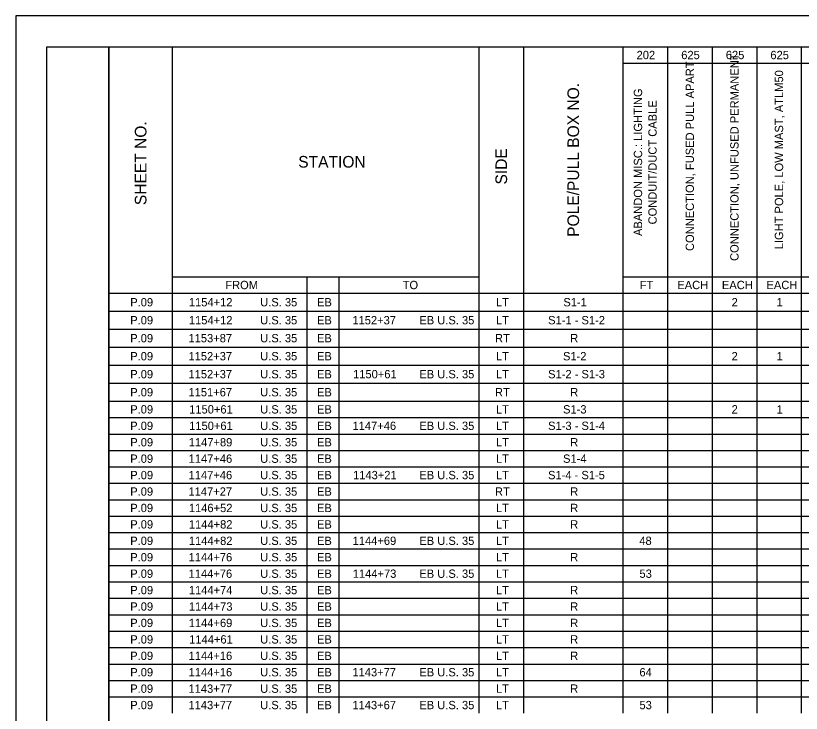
# Model space of a CAD drawing. Extents: x 0 to 34, y 0 to 22.
# Drawn here: x 0 to 12.63, y 10.78 to 22 of the extents above; entities that cross this region are included whole.
import ezdxf

# ---------------------------------------------------------------- set-up
doc = ezdxf.new("R2010")
doc.units = 0
for name, color, linetype in [('Default', 7, 'Continuous'), ('SH_Border', 7, 'Continuous'), ('SH_Cut_Line', 7, 'Continuous')]:
    doc.layers.add(name, color=color, linetype=linetype)

msp = doc.modelspace()

# ---------------------------------------------------------------- linework, layer by layer
at = {"layer": 'Default'}
for p, q in [((1.5, 21.5), (2.519, 21.5)), ((1.5, 21.5), (1.5, 21.236)), ((2.519, 21.5), (4.683, 21.5)), ((2.519, 21.5), (2.519, 21.236)), ((4.683, 21.5), (11.918, 21.5)), ((7.451, 21.5), (7.451, 21.236)), ((8.168, 21.5), (8.168, 21.236)), ((9.766, 21.5), (9.766, 21.236)), ((10.483, 21.5), (10.483, 21.236)), ((11.201, 21.5), (11.201, 21.236)), ((11.918, 21.5), (12.635, 21.5)), ((11.918, 21.5), (11.918, 21.236)), ((12.635, 21.5), (13.352, 21.5)), ((12.635, 21.5), (12.635, 21.236)), ((1.5, 21.236), (1.5, 20.972)), ((2.519, 21.236), (2.519, 20.972)), ((7.451, 21.236), (7.451, 20.972)), ((8.168, 21.236), (8.168, 20.972)), ((9.766, 21.236), (11.918, 21.236)), ((9.766, 21.236), (9.766, 20.972)), ((10.483, 21.236), (10.483, 20.972)), ((11.201, 21.236), (11.201, 20.972)), ((11.918, 21.236), (12.635, 21.236)), ((11.918, 21.236), (11.918, 20.972)), ((12.635, 21.236), (13.352, 21.236)), ((12.635, 21.236), (12.635, 20.972)), ((1.5, 20.972), (1.5, 20.707)), ((2.519, 20.972), (2.519, 20.707)), ((7.451, 20.972), (7.451, 20.707)), ((8.168, 20.972), (8.168, 20.707)), ((9.766, 20.972), (9.766, 20.707)), ((10.483, 20.972), (10.483, 20.707)), ((11.201, 20.972), (11.201, 20.707)), ((11.918, 20.972), (11.918, 20.707)), ((12.635, 20.972), (12.635, 20.707)), ((1.5, 20.707), (1.5, 20.443)), ((2.519, 20.707), (2.519, 20.443)), ((7.451, 20.707), (7.451, 20.443)), ((8.168, 20.707), (8.168, 20.443)), ((9.766, 20.707), (9.766, 20.443)), ((10.483, 20.707), (10.483, 20.443)), ((11.201, 20.707), (11.201, 20.443)), ((11.918, 20.707), (11.918, 20.443)), ((12.635, 20.707), (12.635, 20.443)), ((1.5, 20.443), (1.5, 20.179)), ((2.519, 20.443), (2.519, 20.179)), ((7.451, 20.443), (7.451, 20.179)), ((8.168, 20.443), (8.168, 20.179)), ((9.766, 20.443), (9.766, 20.179)), ((10.483, 20.443), (10.483, 20.179)), ((11.201, 20.443), (11.201, 20.179)), ((11.918, 20.443), (11.918, 20.179)), ((12.635, 20.443), (12.635, 20.179)), ((1.5, 20.179), (1.5, 19.915)), ((2.519, 20.179), (2.519, 19.915)), ((7.451, 20.179), (7.451, 19.915)), ((8.168, 20.179), (8.168, 19.915)), ((9.766, 20.179), (9.766, 19.915)), ((10.483, 20.179), (10.483, 19.915)), ((11.201, 20.179), (11.201, 19.915)), ((11.918, 20.179), (11.918, 19.915)), ((12.635, 20.179), (12.635, 19.915)), ((1.5, 19.915), (1.5, 19.651)), ((2.519, 19.915), (2.519, 19.651)), ((7.451, 19.915), (7.451, 19.651)), ((8.168, 19.915), (8.168, 19.651)), ((9.766, 19.915), (9.766, 19.651)), ((10.483, 19.915), (10.483, 19.651)), ((11.201, 19.915), (11.201, 19.651)), ((11.918, 19.915), (11.918, 19.651)), ((12.635, 19.915), (12.635, 19.651)), ((1.5, 19.651), (1.5, 19.122)), ((2.519, 19.651), (2.519, 19.122)), ((7.451, 19.651), (7.451, 19.122)), ((8.168, 19.651), (8.168, 19.122)), ((9.766, 19.651), (9.766, 19.122)), ((10.483, 19.651), (10.483, 19.122)), ((11.201, 19.651), (11.201, 19.122)), ((11.918, 19.651), (11.918, 19.122)), ((12.635, 19.651), (12.635, 19.122)), ((1.5, 19.122), (1.5, 18.329)), ((2.519, 19.122), (2.519, 18.329)), ((7.451, 19.122), (7.451, 18.329)), ((8.168, 19.122), (8.168, 18.329)), ((9.766, 19.122), (9.766, 18.329)), ((10.483, 19.122), (10.483, 18.329)), ((11.201, 19.122), (11.201, 18.329)), ((11.918, 19.122), (11.918, 18.329)), ((12.635, 19.122), (12.635, 18.329)), ((1.5, 18.329), (1.5, 18.065)), ((2.519, 18.329), (2.519, 18.065)), ((7.451, 18.329), (7.451, 18.065)), ((8.168, 18.329), (8.168, 18.065)), ((9.766, 18.329), (9.766, 18.065)), ((10.483, 18.329), (10.483, 18.065)), ((11.201, 18.329), (11.201, 18.065)), ((11.918, 18.329), (11.918, 18.065)), ((12.635, 18.329), (12.635, 18.065)), ((1.5, 18.065), (1.5, 17.537)), ((2.519, 18.065), (2.519, 17.537)), ((7.451, 18.065), (7.451, 17.537)), ((8.168, 18.065), (8.168, 17.537)), ((9.766, 18.065), (9.766, 17.537)), ((10.483, 18.065), (10.483, 17.537)), ((11.201, 18.065), (11.201, 17.537)), ((11.918, 18.065), (11.918, 17.537)), ((12.635, 18.065), (12.635, 17.537)), ((2.519, 17.801), (4.683, 17.801)), ((4.683, 17.801), (7.451, 17.801)), ((4.683, 17.801), (4.683, 17.537)), ((5.199, 17.801), (5.199, 17.537)), ((9.766, 17.801), (11.918, 17.801)), ((11.918, 17.801), (12.635, 17.801)), ((12.635, 17.801), (13.352, 17.801)), ((1.5, 17.537), (2.519, 17.537)), ((1.5, 17.537), (1.5, 17.247)), ((2.519, 17.537), (4.683, 17.537)), ((2.519, 17.537), (2.519, 17.247)), ((4.683, 17.537), (11.918, 17.537)), ((4.683, 17.537), (4.683, 17.247)), ((5.199, 17.537), (5.199, 17.247)), ((7.451, 17.537), (7.451, 17.247)), ((8.168, 17.537), (8.168, 17.247)), ((9.766, 17.537), (9.766, 17.247)), ((10.483, 17.537), (10.483, 17.247)), ((11.201, 17.537), (11.201, 17.247)), ((11.918, 17.537), (12.635, 17.537)), ((11.918, 17.537), (11.918, 17.247)), ((12.635, 17.537), (13.352, 17.537)), ((12.635, 17.537), (12.635, 17.247)), ((1.5, 17.247), (2.519, 17.247)), ((1.5, 17.247), (1.5, 15.801)), ((2.519, 17.247), (4.683, 17.247)), ((2.519, 17.247), (2.519, 15.801)), ((4.683, 17.247), (11.918, 17.247)), ((4.683, 17.247), (4.683, 15.801)), ((5.199, 17.247), (5.199, 15.801)), ((7.451, 17.247), (7.451, 15.801)), ((8.168, 17.247), (8.168, 15.801)), ((9.766, 17.247), (9.766, 15.801)), ((10.483, 17.247), (10.483, 15.801)), ((11.201, 17.247), (11.201, 15.801)), ((11.918, 17.247), (12.635, 17.247)), ((11.918, 17.247), (11.918, 15.801)), ((12.635, 17.247), (13.352, 17.247)), ((12.635, 17.247), (12.635, 15.801)), ((1.5, 16.958), (2.519, 16.958)), ((2.519, 16.958), (4.683, 16.958)), ((4.683, 16.958), (11.918, 16.958)), ((11.918, 16.958), (12.635, 16.958)), ((12.635, 16.958), (13.352, 16.958)), ((1.5, 16.669), (2.519, 16.669)), ((2.519, 16.669), (4.683, 16.669)), ((4.683, 16.669), (11.918, 16.669)), ((11.918, 16.669), (12.635, 16.669)), ((12.635, 16.669), (13.352, 16.669)), ((1.5, 16.379), (2.519, 16.379)), ((2.519, 16.379), (4.683, 16.379)), ((4.683, 16.379), (11.918, 16.379)), ((11.918, 16.379), (12.635, 16.379)), ((12.635, 16.379), (13.352, 16.379)), ((1.5, 16.09), (2.519, 16.09)), ((2.519, 16.09), (4.683, 16.09)), ((4.683, 16.09), (11.918, 16.09)), ((11.918, 16.09), (12.635, 16.09)), ((12.635, 16.09), (13.352, 16.09)), ((1.5, 15.801), (2.519, 15.801)), ((1.5, 15.801), (1.5, 15.272)), ((2.519, 15.801), (4.683, 15.801)), ((2.519, 15.801), (2.519, 15.272)), ((4.683, 15.801), (11.918, 15.801)), ((4.683, 15.801), (4.683, 15.272)), ((5.199, 15.801), (5.199, 15.272)), ((7.451, 15.801), (7.451, 15.272)), ((8.168, 15.801), (8.168, 15.272)), ((9.766, 15.801), (9.766, 15.272)), ((10.483, 15.801), (10.483, 15.272)), ((11.201, 15.801), (11.201, 15.272)), ((11.918, 15.801), (12.635, 15.801)), ((11.918, 15.801), (11.918, 15.272)), ((12.635, 15.801), (13.352, 15.801)), ((12.635, 15.801), (12.635, 15.272)), ((1.5, 15.536), (2.519, 15.536)), ((2.519, 15.536), (4.683, 15.536)), ((4.683, 15.536), (11.918, 15.536)), ((11.918, 15.536), (12.635, 15.536)), ((12.635, 15.536), (13.352, 15.536)), ((1.5, 15.272), (2.519, 15.272)), ((1.5, 15.272), (1.5, 15.008)), ((2.519, 15.272), (4.683, 15.272)), ((2.519, 15.272), (2.519, 15.008)), ((4.683, 15.272), (11.918, 15.272)), ((4.683, 15.272), (4.683, 15.008)), ((5.199, 15.272), (5.199, 15.008)), ((7.451, 15.272), (7.451, 15.008)), ((8.168, 15.272), (8.168, 15.008)), ((9.766, 15.272), (9.766, 15.008)), ((10.483, 15.272), (10.483, 15.008)), ((11.201, 15.272), (11.201, 15.008)), ((11.918, 15.272), (12.635, 15.272)), ((11.918, 15.272), (11.918, 15.008)), ((12.635, 15.272), (13.352, 15.272)), ((12.635, 15.272), (12.635, 15.008)), ((1.5, 15.008), (2.519, 15.008)), ((1.5, 15.008), (1.5, 14.479)), ((2.519, 15.008), (4.683, 15.008)), ((2.519, 15.008), (2.519, 14.479)), ((4.683, 15.008), (11.918, 15.008)), ((4.683, 15.008), (4.683, 14.479)), ((5.199, 15.008), (5.199, 14.479)), ((7.451, 15.008), (7.451, 14.479)), ((8.168, 15.008), (8.168, 14.479)), ((9.766, 15.008), (9.766, 14.479)), ((10.483, 15.008), (10.483, 14.479)), ((11.201, 15.008), (11.201, 14.479)), ((11.918, 15.008), (12.635, 15.008)), ((11.918, 15.008), (11.918, 14.479)), ((12.635, 15.008), (13.352, 15.008)), ((12.635, 15.008), (12.635, 14.479)), ((1.5, 14.744), (2.519, 14.744)), ((2.519, 14.744), (4.683, 14.744)), ((4.683, 14.744), (11.918, 14.744)), ((11.918, 14.744), (12.635, 14.744)), ((12.635, 14.744), (13.352, 14.744)), ((1.5, 14.479), (2.519, 14.479)), ((1.5, 14.479), (1.5, 13.423)), ((2.519, 14.479), (4.683, 14.479)), ((2.519, 14.479), (2.519, 13.423)), ((4.683, 14.479), (11.918, 14.479)), ((4.683, 14.479), (4.683, 13.423)), ((5.199, 14.479), (5.199, 13.423)), ((7.451, 14.479), (7.451, 13.423)), ((8.168, 14.479), (8.168, 13.423)), ((9.766, 14.479), (9.766, 13.423)), ((10.483, 14.479), (10.483, 13.423)), ((11.201, 14.479), (11.201, 13.423)), ((11.918, 14.479), (12.635, 14.479)), ((11.918, 14.479), (11.918, 13.423)), ((12.635, 14.479), (13.352, 14.479)), ((12.635, 14.479), (12.635, 13.423)), ((1.5, 14.215), (2.519, 14.215)), ((2.519, 14.215), (4.683, 14.215)), ((4.683, 14.215), (11.918, 14.215)), ((11.918, 14.215), (12.635, 14.215)), ((12.635, 14.215), (13.352, 14.215)), ((1.5, 13.951), (2.519, 13.951)), ((2.519, 13.951), (4.683, 13.951)), ((4.683, 13.951), (11.918, 13.951)), ((11.918, 13.951), (12.635, 13.951)), ((12.635, 13.951), (13.352, 13.951)), ((1.5, 13.687), (2.519, 13.687)), ((2.519, 13.687), (4.683, 13.687)), ((4.683, 13.687), (11.918, 13.687)), ((11.918, 13.687), (12.635, 13.687)), ((12.635, 13.687), (13.352, 13.687)), ((1.5, 13.423), (2.519, 13.423)), ((1.5, 13.423), (1.5, 13.158)), ((2.519, 13.423), (4.683, 13.423)), ((2.519, 13.423), (2.519, 13.158)), ((4.683, 13.423), (11.918, 13.423)), ((4.683, 13.423), (4.683, 13.158)), ((5.199, 13.423), (5.199, 13.158)), ((7.451, 13.423), (7.451, 13.158)), ((8.168, 13.423), (8.168, 13.158)), ((9.766, 13.423), (9.766, 13.158)), ((10.483, 13.423), (10.483, 13.158)), ((11.201, 13.423), (11.201, 13.158)), ((11.918, 13.423), (12.635, 13.423)), ((11.918, 13.423), (11.918, 13.158)), ((12.635, 13.423), (13.352, 13.423)), ((12.635, 13.423), (12.635, 13.158)), ((1.5, 13.158), (2.519, 13.158)), ((1.5, 13.158), (1.5, 12.894)), ((2.519, 13.158), (4.683, 13.158)), ((2.519, 13.158), (2.519, 12.894)), ((4.683, 13.158), (11.918, 13.158)), ((4.683, 13.158), (4.683, 12.894)), ((5.199, 13.158), (5.199, 12.894)), ((7.451, 13.158), (7.451, 12.894)), ((8.168, 13.158), (8.168, 12.894)), ((9.766, 13.158), (9.766, 12.894)), ((10.483, 13.158), (10.483, 12.894)), ((11.201, 13.158), (11.201, 12.894)), ((11.918, 13.158), (12.635, 13.158)), ((11.918, 13.158), (11.918, 12.894)), ((12.635, 13.158), (13.352, 13.158)), ((12.635, 13.158), (12.635, 12.894)), ((1.5, 12.894), (2.519, 12.894)), ((1.5, 12.894), (1.5, 12.101)), ((2.519, 12.894), (4.683, 12.894)), ((2.519, 12.894), (2.519, 12.101)), ((4.683, 12.894), (11.918, 12.894)), ((4.683, 12.894), (4.683, 12.101)), ((5.199, 12.894), (5.199, 12.101)), ((7.451, 12.894), (7.451, 12.101)), ((8.168, 12.894), (8.168, 12.101)), ((9.766, 12.894), (9.766, 12.101)), ((10.483, 12.894), (10.483, 12.101)), ((11.201, 12.894), (11.201, 12.101)), ((11.918, 12.894), (12.635, 12.894)), ((11.918, 12.894), (11.918, 12.101)), ((12.635, 12.894), (13.352, 12.894)), ((12.635, 12.894), (12.635, 12.101)), ((1.5, 12.63), (2.519, 12.63)), ((2.519, 12.63), (4.683, 12.63)), ((4.683, 12.63), (11.918, 12.63)), ((11.918, 12.63), (12.635, 12.63)), ((12.635, 12.63), (13.352, 12.63)), ((1.5, 12.366), (2.519, 12.366)), ((2.519, 12.366), (4.683, 12.366)), ((4.683, 12.366), (11.918, 12.366)), ((11.918, 12.366), (12.635, 12.366)), ((12.635, 12.366), (13.352, 12.366)), ((1.5, 12.101), (2.519, 12.101)), ((1.5, 12.101), (1.5, 11.573)), ((2.519, 12.101), (4.683, 12.101)), ((2.519, 12.101), (2.519, 11.573)), ((4.683, 12.101), (11.918, 12.101)), ((4.683, 12.101), (4.683, 11.573)), ((5.199, 12.101), (5.199, 11.573)), ((7.451, 12.101), (7.451, 11.573)), ((8.168, 12.101), (8.168, 11.573)), ((9.766, 12.101), (9.766, 11.573)), ((10.483, 12.101), (10.483, 11.573)), ((11.201, 12.101), (11.201, 11.573)), ((11.918, 12.101), (12.635, 12.101)), ((11.918, 12.101), (11.918, 11.573)), ((12.635, 12.101), (13.352, 12.101)), ((12.635, 12.101), (12.635, 11.573)), ((1.5, 11.837), (2.519, 11.837)), ((2.519, 11.837), (4.683, 11.837)), ((4.683, 11.837), (11.918, 11.837)), ((11.918, 11.837), (12.635, 11.837)), ((12.635, 11.837), (13.352, 11.837)), ((1.5, 11.573), (2.519, 11.573)), ((1.5, 11.573), (1.5, 10.78)), ((2.519, 11.573), (4.683, 11.573)), ((2.519, 11.573), (2.519, 10.78)), ((4.683, 11.573), (11.918, 11.573)), ((4.683, 11.573), (4.683, 10.78)), ((5.199, 11.573), (5.199, 10.78)), ((7.451, 11.573), (7.451, 10.78)), ((8.168, 11.573), (8.168, 10.78)), ((9.766, 11.573), (9.766, 10.78)), ((10.483, 11.573), (10.483, 10.78)), ((11.201, 11.573), (11.201, 10.78)), ((11.918, 11.573), (12.635, 11.573)), ((11.918, 11.573), (11.918, 10.78)), ((12.635, 11.573), (13.352, 11.573)), ((12.635, 11.573), (12.635, 10.78)), ((1.5, 11.309), (2.519, 11.309)), ((2.519, 11.309), (4.683, 11.309)), ((4.683, 11.309), (11.918, 11.309)), ((11.918, 11.309), (12.635, 11.309)), ((12.635, 11.309), (13.352, 11.309)), ((1.5, 11.045), (2.519, 11.045)), ((2.519, 11.045), (4.683, 11.045)), ((4.683, 11.045), (11.918, 11.045)), ((11.918, 11.045), (12.635, 11.045)), ((12.635, 11.045), (13.352, 11.045))]:
    msp.add_line(p, q, dxfattribs=at)
at = {"layer": 'SH_Border'}
for points in [[(0.5, 21.5), (1.5, 21.5), (1.5, 0.5), (0.5, 0.5)], [(1.5, 21.5), (33.5, 21.5), (33.5, 0.5), (1.5, 0.5)]]:
    msp.add_lwpolyline(points, close=True, dxfattribs=at)
at = {"layer": 'SH_Cut_Line'}
msp.add_lwpolyline([(0, 0), (34, 0), (34, 22), (0, 22)], close=True, dxfattribs=at)

# ---------------------------------------------------------------- texts
at = {"layer": 'Default'}
for s, height, p in [('202', 0.1337, (9.986, 21.301)), ('625', 0.1337, (10.704, 21.301)), ('625', 0.1337, (11.421, 21.301)), ('625', 0.1337, (12.138, 21.301)), ('STATION', 0.1872, (4.544, 19.557)), ('FROM', 0.1337, (3.371, 17.602)), ('TO', 0.1337, (6.224, 17.602)), ('FT', 0.1337, (10.036, 17.602)), ('EACH', 0.1337, (10.641, 17.602)), ('EACH', 0.1337, (11.358, 17.602)), ('EACH', 0.1337, (12.075, 17.602)), ('P.09', 0.1337, (1.842, 17.325)), ('1154+12', 0.1337, (2.785, 17.325)), ('U.S. 35', 0.1337, (3.932, 17.325)), ('EB', 0.1337, (4.846, 17.325)), ('LT', 0.1337, (7.725, 17.325)), ('S1-1', 0.1337, (8.808, 17.325)), ('2', 0.134, (11.514, 17.325)), ('1', 0.134, (12.237, 17.325)), ('P.09', 0.1337, (1.842, 17.036)), ('1154+12', 0.1337, (2.785, 17.036)), ('U.S. 35', 0.1337, (3.932, 17.036)), ('EB', 0.1337, (4.846, 17.036)), ('1152+37', 0.1337, (5.415, 17.036)), ('EB U.S. 35', 0.1337, (6.492, 17.036)), ('LT', 0.1337, (7.725, 17.036)), ('S1-1 - S1-2', 0.13368, (8.563, 17.036)), ('P.09', 0.1337, (1.842, 16.747)), ('1153+87', 0.1337, (2.779, 16.747)), ('U.S. 35', 0.1337, (3.932, 16.747)), ('EB', 0.1337, (4.846, 16.747)), ('RT', 0.1337, (7.708, 16.747)), ('R', 0.134, (8.918, 16.747)), ('P.09', 0.1337, (1.842, 16.457)), ('1152+37', 0.1337, (2.779, 16.457)), ('U.S. 35', 0.1337, (3.932, 16.457)), ('EB', 0.1337, (4.846, 16.457)), ('LT', 0.1337, (7.725, 16.457)), ('S1-2', 0.1337, (8.802, 16.457)), ('2', 0.134, (11.514, 16.457)), ('1', 0.134, (12.237, 16.457)), ('P.09', 0.1337, (1.842, 16.168)), ('1152+37', 0.1337, (2.779, 16.168)), ('U.S. 35', 0.1337, (3.932, 16.168)), ('EB', 0.1337, (4.846, 16.168)), ('1150+61', 0.1337, (5.426, 16.168)), ('EB U.S. 35', 0.1337, (6.492, 16.168)), ('LT', 0.1337, (7.725, 16.168)), ('S1-2 - S1-3', 0.13368, (8.563, 16.168)), ('P.09', 0.1337, (1.842, 15.878)), ('1151+67', 0.1337, (2.779, 15.878)), ('U.S. 35', 0.1337, (3.932, 15.878)), ('EB', 0.1337, (4.846, 15.878)), ('RT', 0.1337, (7.708, 15.878)), ('R', 0.134, (8.918, 15.878)), ('P.09', 0.1337, (1.842, 15.602)), ('1150+61', 0.1337, (2.79, 15.602)), ('U.S. 35', 0.1337, (3.932, 15.602)), ('EB', 0.1337, (4.846, 15.602)), ('LT', 0.1337, (7.725, 15.602)), ('S1-3', 0.1337, (8.803, 15.602)), ('2', 0.134, (11.514, 15.602)), ('1', 0.134, (12.237, 15.602)), ('P.09', 0.1337, (1.842, 15.337)), ('1150+61', 0.1337, (2.79, 15.337)), ('U.S. 35', 0.1337, (3.932, 15.337)), ('EB', 0.1337, (4.846, 15.337)), ('1147+46', 0.1337, (5.417, 15.337)), ('EB U.S. 35', 0.1337, (6.492, 15.337)), ('LT', 0.1337, (7.725, 15.337)), ('S1-3 - S1-4', 0.13368, (8.563, 15.337)), ('P.09', 0.1337, (1.842, 15.073)), ('1147+89', 0.1337, (2.783, 15.073)), ('U.S. 35', 0.1337, (3.932, 15.073)), ('EB', 0.1337, (4.846, 15.073)), ('LT', 0.1337, (7.725, 15.073)), ('R', 0.134, (8.918, 15.073)), ('P.09', 0.1337, (1.842, 14.809)), ('1147+46', 0.1337, (2.781, 14.809)), ('U.S. 35', 0.1337, (3.932, 14.809)), ('EB', 0.1337, (4.846, 14.809)), ('LT', 0.1337, (7.725, 14.809)), ('S1-4', 0.1337, (8.803, 14.809)), ('P.09', 0.1337, (1.842, 14.545)), ('1147+46', 0.1337, (2.781, 14.545)), ('U.S. 35', 0.1337, (3.932, 14.545)), ('EB', 0.1337, (4.846, 14.545)), ('1143+21', 0.1337, (5.426, 14.545)), ('EB U.S. 35', 0.1337, (6.492, 14.545)), ('LT', 0.1337, (7.725, 14.545)), ('S1-4 - S1-5', 0.13368, (8.562, 14.545)), ('P.09', 0.1337, (1.842, 14.28)), ('1147+27', 0.1337, (2.779, 14.28)), ('U.S. 35', 0.1337, (3.932, 14.28)), ('EB', 0.1337, (4.846, 14.28)), ('RT', 0.1337, (7.708, 14.28)), ('R', 0.134, (8.918, 14.28)), ('P.09', 0.1337, (1.842, 14.016)), ('1146+52', 0.1337, (2.785, 14.016)), ('U.S. 35', 0.1337, (3.932, 14.016)), ('EB', 0.1337, (4.846, 14.016)), ('LT', 0.1337, (7.725, 14.016)), ('R', 0.134, (8.918, 14.016)), ('P.09', 0.1337, (1.842, 13.752)), ('1144+82', 0.1337, (2.785, 13.752)), ('U.S. 35', 0.1337, (3.932, 13.752)), ('EB', 0.1337, (4.846, 13.752)), ('LT', 0.1337, (7.725, 13.752)), ('R', 0.134, (8.918, 13.752)), ('P.09', 0.1337, (1.842, 13.488)), ('1144+82', 0.1337, (2.785, 13.488)), ('U.S. 35', 0.1337, (3.932, 13.488)), ('EB', 0.1337, (4.846, 13.488)), ('1144+69', 0.1337, (5.419, 13.488)), ('EB U.S. 35', 0.1337, (6.492, 13.488)), ('LT', 0.1337, (7.725, 13.488)), ('48', 0.1337, (10.03, 13.488)), ('P.09', 0.1337, (1.842, 13.224)), ('1144+76', 0.1337, (2.781, 13.224)), ('U.S. 35', 0.1337, (3.932, 13.224)), ('EB', 0.1337, (4.846, 13.224)), ('LT', 0.1337, (7.725, 13.224)), ('R', 0.134, (8.918, 13.224)), ('P.09', 0.1337, (1.842, 12.959)), ('1144+76', 0.1337, (2.781, 12.959)), ('U.S. 35', 0.1337, (3.932, 12.959)), ('EB', 0.1337, (4.846, 12.959)), ('1144+73', 0.1337, (5.421, 12.959)), ('EB U.S. 35', 0.1337, (6.492, 12.959)), ('LT', 0.1337, (7.725, 12.959)), ('53', 0.1337, (10.032, 12.959)), ('P.09', 0.1337, (1.842, 12.695)), ('1144+74', 0.1337, (2.785, 12.695)), ('U.S. 35', 0.1337, (3.932, 12.695)), ('EB', 0.1337, (4.846, 12.695)), ('LT', 0.1337, (7.725, 12.695)), ('R', 0.134, (8.918, 12.695)), ('P.09', 0.1337, (1.842, 12.431)), ('1144+73', 0.1337, (2.785, 12.431)), ('U.S. 35', 0.1337, (3.932, 12.431)), ('EB', 0.1337, (4.846, 12.431)), ('LT', 0.1337, (7.725, 12.431)), ('R', 0.134, (8.918, 12.431)), ('P.09', 0.1337, (1.842, 12.167)), ('1144+69', 0.1337, (2.783, 12.167)), ('U.S. 35', 0.1337, (3.932, 12.167)), ('EB', 0.1337, (4.846, 12.167)), ('LT', 0.1337, (7.725, 12.167)), ('R', 0.134, (8.918, 12.167)), ('P.09', 0.1337, (1.842, 11.902)), ('1144+61', 0.1337, (2.79, 11.902)), ('U.S. 35', 0.1337, (3.932, 11.902)), ('EB', 0.1337, (4.846, 11.902)), ('LT', 0.1337, (7.725, 11.902)), ('R', 0.134, (8.918, 11.902)), ('P.09', 0.1337, (1.842, 11.638)), ('1144+16', 0.1337, (2.781, 11.638)), ('U.S. 35', 0.1337, (3.932, 11.638)), ('EB', 0.1337, (4.846, 11.638)), ('LT', 0.1337, (7.725, 11.638)), ('R', 0.134, (8.918, 11.638)), ('P.09', 0.1337, (1.842, 11.374)), ('1144+16', 0.1337, (2.781, 11.374)), ('U.S. 35', 0.1337, (3.932, 11.374)), ('EB', 0.1337, (4.846, 11.374)), ('1143+77', 0.1337, (5.415, 11.374)), ('EB U.S. 35', 0.1337, (6.492, 11.374)), ('LT', 0.1337, (7.725, 11.374)), ('64', 0.1337, (10.032, 11.374)), ('P.09', 0.1337, (1.842, 11.11)), ('1143+77', 0.1337, (2.779, 11.11)), ('U.S. 35', 0.1337, (3.932, 11.11)), ('EB', 0.1337, (4.846, 11.11)), ('LT', 0.1337, (7.725, 11.11)), ('R', 0.134, (8.918, 11.11)), ('P.09', 0.1337, (1.842, 10.846)), ('1143+77', 0.1337, (2.779, 10.846)), ('U.S. 35', 0.1337, (3.932, 10.846)), ('EB', 0.1337, (4.846, 10.846)), ('1143+67', 0.1337, (5.415, 10.846)), ('EB U.S. 35', 0.1337, (6.492, 10.846)), ('LT', 0.1337, (7.725, 10.846)), ('53', 0.1337, (10.032, 10.846))]:
    msp.add_text(s, height=height, dxfattribs=at).set_placement(p)
for s, height, p in [('CONNECTION, UNFUSED PERMANENT', 0.13368, (11.626, 18.056)), ('CONNECTION, FUSED PULL APART', 0.13368, (10.909, 18.216)), ('LIGHT POLE, LOW MAST, ATLM50', 0.13368, (12.343, 18.243)), ('POLE/PULL BOX NO.', 0.18715, (9.061, 18.443)), ('ABANDON MISC.: LIGHTING ', 0.13368, (10.075, 18.457)), ('CONDUIT/DUCT CABLE', 0.13368, (10.309, 18.643)), ('SHEET NO.', 0.1872, (2.103, 18.953)), ('SIDE', 0.1872, (7.903, 19.285))]:
    msp.add_text(s, height=height, rotation=90, dxfattribs=at).set_placement(p)

doc.saveas('drawing.dxf')
